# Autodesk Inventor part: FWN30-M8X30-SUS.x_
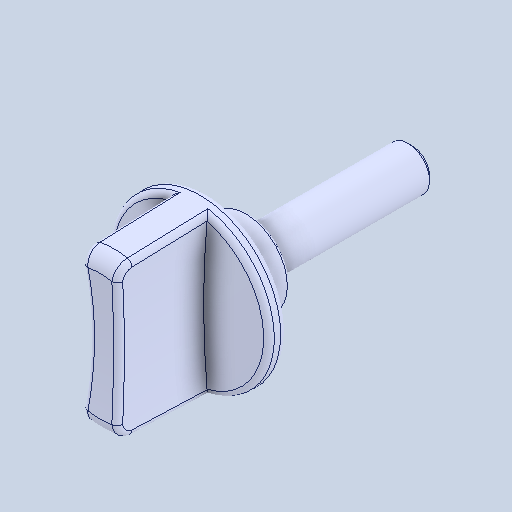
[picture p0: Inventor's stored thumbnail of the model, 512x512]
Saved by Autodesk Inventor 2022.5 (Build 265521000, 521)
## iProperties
Created: 2024-05
Part Number: FWN30-M8X30-SUS.x_
Material: 一般
Document SubType Name: Modeling
Designer: ImaoCorp
Density: 1 g/cm^3
Appearance: 既定
Author: ImaoCorp
Sending System: SOLIDWORKS 2022-2022290
MC: AMD64
MC_MODEL: Intel64 Family 6 Model 60 Stepping 3, GenuineIntel
OS: Windows_NT
FRU: Parasolid Version 33.1, build 260,  4-25-2022
FORMAT: text
GUISE: transmit
KEY: FILEFWN30-M8X30-SUS.x_t
DATE: Mon May 20 16:40:22 2024
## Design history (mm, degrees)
feature "Base1"
node "ソリッド1"
